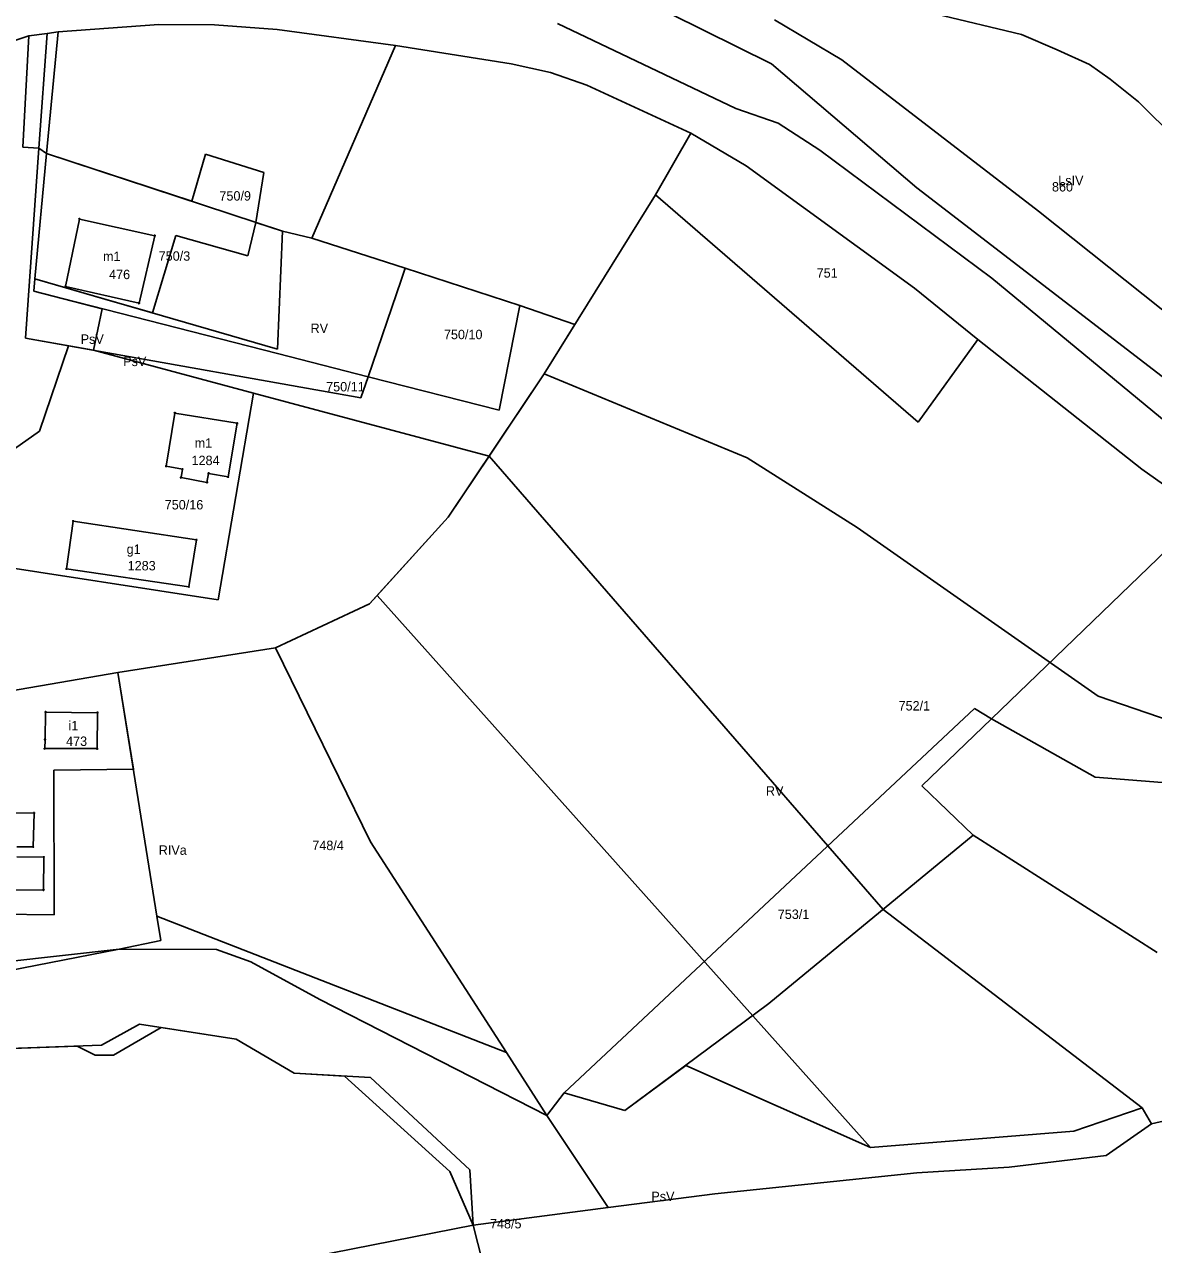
# Model space of a CAD drawing. Extents: x 7498273 to 7499989, y 5499795 to 5500810.
# Drawn here: x 7498893.9 to 7499073.7, y 5500326.8 to 5500521 of the extents above; entities that cross this region are included whole.
import ezdxf

# ---------------------------------------------------------------- set-up
doc = ezdxf.new("R2010")
doc.units = 0
for name, color, linetype in [('209-oznaczenie konturu klasyfikacyjnego', 7, 'Continuous'), ('211-numer działki ewidencyjnej', 7, 'Continuous'), ('217-kontur klasyfikacyjny', 7, 'Continuous'), ('218-kontur użytku gruntowego', 7, 'Continuous'), ('219-działka ewidencyjna', 7, 'Continuous'), ('312-budynek ewidencyjny', 7, 'Continuous'), ('312-oznaczenie budynku ewidencyjnego', 7, 'Continuous'), ('312-oznaczenie budynku ewidencyjnego-Atr117', 7, 'Continuous'), ('Punkt budynku', 7, 'Continuous')]:
    doc.layers.add(name, color=color, linetype=linetype)

# ---------------------------------------------------------------- blocks, each defined once
blk = doc.blocks.new('PUNKTBUD')
blk.add_circle((0, 0), 0.09)

msp = doc.modelspace()

# ---------------------------------------------------------------- linework, layer by layer
at = {"layer": '217-kontur klasyfikacyjny'}
for points in [[(7499052.63, 5500519.38), (7499025.15, 5500526.01)], [(7499013.3, 5500521.7), (7499024.04, 5500515.33)], [(7498897.49, 5500519.54), (7498894.59, 5500519.13)], [(7498899.25, 5500519.79), (7498897.49, 5500519.54)], [(7498915.29, 5500520.95), (7498899.25, 5500519.79)], [(7498924.13, 5500520.89), (7498915.29, 5500520.95)], [(7498934.14, 5500520.18), (7498924.13, 5500520.89)], [(7498952.96, 5500517.64), (7498934.14, 5500520.18)], [(7499058.33, 5500516.93), (7499052.63, 5500519.38)], [(7498894.59, 5500519.13), (7498885.18, 5500516.08)], [(7498971.38, 5500514.69), (7498952.96, 5500517.64)], [(7499024.04, 5500515.33), (7499055.34, 5500491.27)], [(7499063.46, 5500514.6), (7499058.33, 5500516.93)], [(7498977.66, 5500513.32), (7498971.38, 5500514.69)], [(7499066.72, 5500512.27), (7499063.46, 5500514.6)], [(7498983.45, 5500511.3), (7498977.66, 5500513.32)], [(7499071.27, 5500508.65), (7499066.72, 5500512.27)], [(7499000.01, 5500503.64), (7498983.45, 5500511.3)], [(7499101.66, 5500478.53), (7499071.27, 5500508.65)], [(7499008.77, 5500498.48), (7499000.01, 5500503.64)], [(7498893.65, 5500501.42), (7498896.19, 5500501.25)], [(7498896.19, 5500501.25), (7498894.04, 5500471.05)], [(7498895.55, 5500480.48), (7498897.42, 5500500.41)], [(7498897.42, 5500500.41), (7498896.19, 5500501.25)], [(7498897.42, 5500500.41), (7498920.54, 5500492.82)], [(7498920.54, 5500492.82), (7498922.7, 5500500.32)], [(7498922.7, 5500500.32), (7498932.02, 5500497.39)], [(7499035.61, 5500479), (7499008.77, 5500498.48)], [(7498932.02, 5500497.39), (7498930.74, 5500489.47)], [(7499055.34, 5500491.27), (7499080.34, 5500471.35)], [(7498930.74, 5500489.47), (7498929.44, 5500484.15)], [(7498934.98, 5500488.08), (7498930.74, 5500489.47)], [(7498918.01, 5500487.35), (7498914.31, 5500475.05)], [(7498929.44, 5500484.15), (7498918.01, 5500487.35)], [(7498939.66, 5500486.96), (7498934.98, 5500488.08)], [(7498954.51, 5500482.16), (7498939.66, 5500486.96)], [(7498895.37, 5500478.49), (7498895.55, 5500480.48)], [(7498906.68, 5500477.26), (7498895.55, 5500480.48)], [(7498972.75, 5500476.25), (7498954.51, 5500482.16)], [(7498906.28, 5500475.71), (7498895.37, 5500478.49)], [(7499045.66, 5500470.84), (7499035.61, 5500479)], [(7498914.31, 5500475.05), (7498906.68, 5500477.26)], [(7498904.87, 5500469.13), (7498906.28, 5500475.71)], [(7498981.53, 5500473.22), (7498972.75, 5500476.25)], [(7498976.63, 5500465.35), (7498981.53, 5500473.22)], [(7498894.04, 5500471.05), (7498904.87, 5500469.13)], [(7499071.81, 5500450.17), (7499045.66, 5500470.84)], [(7498904.87, 5500469.13), (7498930.36, 5500462.29)], [(7498976.63, 5500465.35), (7498967.86, 5500452.25)], [(7499008.94, 5500452.01), (7498976.63, 5500465.35)], [(7498930.36, 5500462.29), (7498924.73, 5500429.39)], [(7498930.36, 5500462.29), (7498967.86, 5500452.25)], [(7498967.86, 5500452.25), (7498961.36, 5500442.54)], [(7498967.86, 5500452.25), (7499030.59, 5500380.1)], [(7499026.48, 5500440.9), (7499008.94, 5500452.01)], [(7499081.74, 5500443.12), (7499071.81, 5500450.17)], [(7498961.36, 5500442.54), (7498950.04, 5500430.08)], [(7499064.84, 5500414.07), (7499026.48, 5500440.9)], [(7498924.73, 5500429.39), (7498886.87, 5500435.24)], [(7498950.04, 5500430.08), (7498948.84, 5500428.77)], [(7498950.04, 5500430.08), (7499028.61, 5500342.19)], [(7498948.84, 5500428.77), (7498933.86, 5500421.77)], [(7498933.86, 5500421.77), (7498908.79, 5500417.83)], [(7498883.78, 5500413.51), (7498908.79, 5500417.83)], [(7498908.79, 5500417.83), (7498911.24, 5500402.45)], [(7499090.07, 5500405.4), (7499064.84, 5500414.07)], [(7498911.24, 5500402.45), (7498898.57, 5500402.29)], [(7498898.57, 5500402.29), (7498898.64, 5500379.25)], [(7498898.64, 5500379.25), (7498881.05, 5500379.45)], [(7499030.59, 5500380.1), (7499071.84, 5500348.54)], [(7498908.98, 5500373.76), (7498863.81, 5500368.75)], [(7498924.46, 5500373.71), (7498908.98, 5500373.76)], [(7498929.93, 5500371.77), (7498924.46, 5500373.71)], [(7498940.91, 5500365.79), (7498929.93, 5500371.77)], [(7498977.07, 5500347.3), (7498940.91, 5500365.79)], [(7498915.64, 5500361.32), (7498908.07, 5500356.93)], [(7498927.58, 5500359.44), (7498915.64, 5500361.32)], [(7498902.28, 5500358.34), (7498888.92, 5500357.87)], [(7498905.14, 5500356.92), (7498902.28, 5500358.34)], [(7498936.85, 5500354.04), (7498927.58, 5500359.44)], [(7498908.07, 5500356.93), (7498905.14, 5500356.92)], [(7498999.17, 5500355.28), (7498989.5, 5500348.09)], [(7499028.61, 5500342.19), (7498999.17, 5500355.28)], [(7498944.86, 5500353.58), (7498936.85, 5500354.04)], [(7498961.64, 5500338.37), (7498944.86, 5500353.58)], [(7498979.8, 5500350.9), (7498977.07, 5500347.3)], [(7498989.5, 5500348.09), (7498979.8, 5500350.9)], [(7499060.98, 5500344.83), (7499071.84, 5500348.54)], [(7499071.84, 5500348.54), (7499073.33, 5500345.99)], [(7498977.07, 5500347.3), (7498986.83, 5500332.68)], [(7499028.61, 5500342.19), (7499060.98, 5500344.83)], [(7499073.33, 5500345.99), (7499066.13, 5500340.92)], [(7499066.13, 5500340.92), (7499050.64, 5500339.09)], [(7499050.64, 5500339.09), (7499035.94, 5500338.2)], [(7498965.33, 5500329.84), (7498961.64, 5500338.37)], [(7499035.94, 5500338.2), (7499003.8, 5500334.85)], [(7499003.8, 5500334.85), (7498986.83, 5500332.68)], [(7498986.83, 5500332.68), (7498965.33, 5500329.84)]]:
    msp.add_lwpolyline(points, dxfattribs=at)
at = {"layer": '218-kontur użytku gruntowego'}
for points in [[(7499012.84, 5500514.68), (7498991.26, 5500525.39)], [(7499052.63, 5500519.38), (7499025.15, 5500526.01)], [(7499013.3, 5500521.7), (7499024.04, 5500515.33)], [(7498894.59, 5500519.13), (7498897.49, 5500519.54)], [(7498897.49, 5500519.54), (7498899.25, 5500519.79)], [(7498899.25, 5500519.79), (7498915.29, 5500520.95)], [(7498915.29, 5500520.95), (7498924.13, 5500520.89)], [(7498924.13, 5500520.89), (7498934.14, 5500520.18)], [(7498934.14, 5500520.18), (7498952.96, 5500517.64)], [(7499007.17, 5500507.58), (7498978.75, 5500521.1)], [(7499058.33, 5500516.93), (7499052.63, 5500519.38)], [(7498885.18, 5500516.08), (7498894.59, 5500519.13)], [(7498952.96, 5500517.64), (7498971.38, 5500514.69)], [(7499024.04, 5500515.33), (7499055.34, 5500491.27)], [(7499063.46, 5500514.6), (7499058.33, 5500516.93)], [(7498971.38, 5500514.69), (7498977.66, 5500513.32)], [(7499035.99, 5500494.95), (7499012.84, 5500514.68)], [(7499066.72, 5500512.27), (7499063.46, 5500514.6)], [(7498977.66, 5500513.32), (7498983.45, 5500511.3)], [(7499071.27, 5500508.65), (7499066.72, 5500512.27)], [(7498983.45, 5500511.3), (7499000.01, 5500503.64)], [(7499013.89, 5500505.24), (7499007.17, 5500507.58)], [(7499101.66, 5500478.53), (7499071.27, 5500508.65)], [(7499020.5, 5500500.94), (7499013.89, 5500505.24)], [(7499000.01, 5500503.64), (7499008.77, 5500498.48)], [(7498893.65, 5500501.42), (7498896.19, 5500501.25)], [(7498896.19, 5500501.25), (7498894.04, 5500471.05)], [(7498895.55, 5500480.48), (7498897.42, 5500500.41)], [(7498897.42, 5500500.41), (7498896.19, 5500501.25)], [(7498920.54, 5500492.82), (7498897.42, 5500500.41)], [(7498922.7, 5500500.32), (7498920.54, 5500492.82)], [(7498932.02, 5500497.39), (7498922.7, 5500500.32)], [(7499047.93, 5500480.59), (7499020.5, 5500500.94)], [(7499008.77, 5500498.48), (7499035.61, 5500479)], [(7498930.74, 5500489.47), (7498932.02, 5500497.39)], [(7499085.38, 5500457), (7499035.99, 5500494.95)], [(7499055.34, 5500491.27), (7499080.34, 5500471.35)], [(7498930.74, 5500489.47), (7498929.44, 5500484.15)], [(7498934.98, 5500488.08), (7498930.74, 5500489.47)], [(7498918.01, 5500487.35), (7498914.31, 5500475.05)], [(7498929.44, 5500484.15), (7498918.01, 5500487.35)], [(7498939.66, 5500486.96), (7498934.98, 5500488.08)], [(7498954.51, 5500482.16), (7498939.66, 5500486.96)], [(7498895.37, 5500478.49), (7498895.55, 5500480.48)], [(7498906.68, 5500477.26), (7498895.55, 5500480.48)], [(7498972.75, 5500476.25), (7498954.51, 5500482.16)], [(7499079.66, 5500454.39), (7499047.93, 5500480.59)], [(7498906.28, 5500475.71), (7498895.37, 5500478.49)], [(7499035.61, 5500479), (7499045.66, 5500470.84)], [(7498914.31, 5500475.05), (7498906.68, 5500477.26)], [(7498904.87, 5500469.13), (7498906.28, 5500475.71)], [(7498981.53, 5500473.22), (7498972.75, 5500476.25)], [(7498976.63, 5500465.35), (7498981.53, 5500473.22)], [(7498894.04, 5500471.05), (7498904.87, 5500469.13)], [(7499045.66, 5500470.84), (7499071.81, 5500450.17)], [(7498904.87, 5500469.13), (7498930.36, 5500462.29)], [(7498967.86, 5500452.25), (7498976.63, 5500465.35)], [(7499008.94, 5500452.01), (7498976.63, 5500465.35)], [(7498930.36, 5500462.29), (7498924.73, 5500429.39)], [(7498930.36, 5500462.29), (7498967.86, 5500452.25)], [(7498967.86, 5500452.25), (7498961.36, 5500442.54)], [(7499030.59, 5500380.1), (7498967.86, 5500452.25)], [(7499026.48, 5500440.9), (7499008.94, 5500452.01)], [(7499071.81, 5500450.17), (7499081.74, 5500443.12)], [(7498961.36, 5500442.54), (7498950.04, 5500430.08)], [(7499064.84, 5500414.07), (7499026.48, 5500440.9)], [(7498924.73, 5500429.39), (7498886.87, 5500435.24)], [(7498950.04, 5500430.08), (7498948.84, 5500428.77)], [(7498950.04, 5500430.08), (7499028.61, 5500342.19)], [(7498948.84, 5500428.77), (7498933.86, 5500421.77)], [(7498933.86, 5500421.77), (7498908.79, 5500417.83)], [(7498908.79, 5500417.83), (7498883.78, 5500413.51)], [(7498911.24, 5500402.45), (7498908.79, 5500417.83)], [(7499090.07, 5500405.4), (7499064.84, 5500414.07)], [(7498898.57, 5500402.29), (7498911.24, 5500402.45)], [(7498898.64, 5500379.25), (7498898.57, 5500402.29)], [(7498881.05, 5500379.45), (7498898.64, 5500379.25)], [(7499071.84, 5500348.54), (7499030.59, 5500380.1)], [(7498908.98, 5500373.76), (7498863.81, 5500368.75)], [(7498924.46, 5500373.71), (7498908.98, 5500373.76)], [(7498929.93, 5500371.77), (7498924.46, 5500373.71)], [(7498940.91, 5500365.79), (7498929.93, 5500371.77)], [(7498977.07, 5500347.3), (7498940.91, 5500365.79)], [(7498915.64, 5500361.32), (7498908.07, 5500356.93)], [(7498927.58, 5500359.44), (7498915.64, 5500361.32)], [(7498902.28, 5500358.34), (7498888.92, 5500357.87)], [(7498905.14, 5500356.92), (7498902.28, 5500358.34)], [(7498936.85, 5500354.04), (7498927.58, 5500359.44)], [(7498908.07, 5500356.93), (7498905.14, 5500356.92)], [(7498999.17, 5500355.28), (7498989.5, 5500348.09)], [(7499028.61, 5500342.19), (7498999.17, 5500355.28)], [(7498944.86, 5500353.58), (7498936.85, 5500354.04)], [(7498961.64, 5500338.37), (7498944.86, 5500353.58)], [(7498979.8, 5500350.9), (7498977.07, 5500347.3)], [(7498989.5, 5500348.09), (7498979.8, 5500350.9)], [(7499071.84, 5500348.54), (7499060.98, 5500344.83)], [(7499073.33, 5500345.99), (7499071.84, 5500348.54)], [(7498977.07, 5500347.3), (7498986.83, 5500332.68)], [(7499060.98, 5500344.83), (7499028.61, 5500342.19)], [(7499066.13, 5500340.92), (7499073.33, 5500345.99)], [(7499050.64, 5500339.09), (7499066.13, 5500340.92)], [(7499035.94, 5500338.2), (7499050.64, 5500339.09)], [(7498965.33, 5500329.84), (7498961.64, 5500338.37)], [(7499003.8, 5500334.85), (7499035.94, 5500338.2)], [(7498986.83, 5500332.68), (7499003.8, 5500334.85)], [(7498986.83, 5500332.68), (7498965.33, 5500329.84)]]:
    msp.add_lwpolyline(points, dxfattribs=at)
at = {"layer": '219-działka ewidencyjna'}
for points in [[(7499052.63, 5500519.38), (7499025.15, 5500526.01)], [(7499024.04, 5500515.33), (7499013.3, 5500521.7)], [(7498894.59, 5500519.13), (7498897.49, 5500519.54)], [(7498896.19, 5500501.25), (7498897.49, 5500519.54)], [(7498897.42, 5500500.41), (7498899.25, 5500519.79)], [(7498897.49, 5500519.54), (7498899.25, 5500519.79)], [(7498915.29, 5500520.95), (7498899.25, 5500519.79)], [(7498915.29, 5500520.95), (7498924.13, 5500520.89)], [(7498924.13, 5500520.89), (7498934.14, 5500520.18)], [(7498934.14, 5500520.18), (7498952.96, 5500517.64)], [(7499052.63, 5500519.38), (7499058.33, 5500516.93)], [(7498885.18, 5500516.08), (7498894.59, 5500519.13)], [(7498894.59, 5500519.13), (7498893.65, 5500501.42)], [(7498939.66, 5500486.96), (7498952.96, 5500517.64)], [(7498952.96, 5500517.64), (7498971.38, 5500514.69)], [(7499024.04, 5500515.33), (7499055.34, 5500491.27)], [(7499058.33, 5500516.93), (7499063.46, 5500514.6)], [(7498977.66, 5500513.32), (7498971.38, 5500514.69)], [(7499063.46, 5500514.6), (7499066.72, 5500512.27)], [(7498977.66, 5500513.32), (7498983.45, 5500511.3)], [(7499066.72, 5500512.27), (7499071.27, 5500508.65)], [(7498983.45, 5500511.3), (7499000.01, 5500503.64)], [(7499071.27, 5500508.65), (7499101.66, 5500478.53)], [(7499000.01, 5500503.64), (7498994.38, 5500493.86)], [(7499000.01, 5500503.64), (7499008.77, 5500498.48)], [(7498894.04, 5500471.05), (7498896.19, 5500501.25)], [(7498895.55, 5500480.48), (7498897.42, 5500500.41)], [(7498934.98, 5500488.08), (7498897.42, 5500500.41)], [(7499008.77, 5500498.48), (7499035.61, 5500479)], [(7498976.63, 5500465.35), (7498994.38, 5500493.86)], [(7498994.38, 5500493.86), (7499036.19, 5500457.69)], [(7499055.34, 5500491.27), (7499080.34, 5500471.35)], [(7498934.98, 5500488.08), (7498934.19, 5500469.3)], [(7498939.66, 5500486.96), (7498954.51, 5500482.16)], [(7498895.37, 5500478.49), (7498895.55, 5500480.48)], [(7498895.55, 5500480.48), (7498934.19, 5500469.3)], [(7498953.87, 5500480.26), (7498954.51, 5500482.16)], [(7498954.51, 5500482.16), (7498972.75, 5500476.25)], [(7498895.37, 5500478.49), (7498934.16, 5500468.59)], [(7498948.61, 5500464.9), (7498953.87, 5500480.26)], [(7499035.61, 5500479), (7499045.66, 5500470.84)], [(7498969.49, 5500459.58), (7498972.75, 5500476.25)], [(7498894.04, 5500471.05), (7498900.92, 5500469.81)], [(7499036.19, 5500457.69), (7499045.66, 5500470.84)], [(7499045.66, 5500470.84), (7499071.81, 5500450.17)], [(7498896.27, 5500456.23), (7498900.92, 5500469.81)], [(7498947.47, 5500461.56), (7498900.92, 5500469.81)], [(7498934.16, 5500468.59), (7498948.61, 5500464.9)], [(7498947.47, 5500461.56), (7498948.61, 5500464.9)], [(7498948.61, 5500464.9), (7498969.49, 5500459.58)], [(7498961.36, 5500442.54), (7498976.63, 5500465.35)], [(7498890.52, 5500452.15), (7498896.27, 5500456.23)], [(7499071.81, 5500450.17), (7499081.74, 5500443.12)], [(7498948.84, 5500428.77), (7498961.36, 5500442.54)], [(7499058.06, 5500420.25), (7499081.74, 5500443.12)], [(7498933.86, 5500421.77), (7498948.84, 5500428.77)], [(7498908.79, 5500417.83), (7498933.86, 5500421.77)], [(7498933.86, 5500421.77), (7498948.98, 5500390.87)], [(7499047.85, 5500410.45), (7499058.06, 5500420.25)], [(7498883.78, 5500413.51), (7498908.79, 5500417.83)], [(7498908.79, 5500417.83), (7498914.96, 5500379.03)], [(7498979.8, 5500350.9), (7499045.13, 5500412.08)], [(7499036.75, 5500399.8), (7499047.85, 5500410.45)], [(7499045.13, 5500412.08), (7499047.85, 5500410.45)], [(7499047.85, 5500410.45), (7499064.37, 5500401.18)], [(7499064.37, 5500401.18), (7499079.03, 5500399.99)], [(7499036.75, 5500399.8), (7499044.92, 5500391.92)], [(7499012.42, 5500365.12), (7499044.92, 5500391.92)], [(7499044.92, 5500391.92), (7499074.23, 5500373.25)], [(7498948.98, 5500390.87), (7498970.66, 5500357.32)], [(7498914.96, 5500379.03), (7498915.63, 5500375.16)], [(7498914.96, 5500379.03), (7498970.66, 5500357.32)], [(7498908.98, 5500373.76), (7498810.76, 5500354.62)], [(7498908.98, 5500373.76), (7498915.63, 5500375.16)], [(7499012.42, 5500365.12), (7498989.5, 5500348.09)], [(7498906.19, 5500358.48), (7498912.2, 5500361.86)], [(7498912.2, 5500361.86), (7498927.58, 5500359.44)], [(7498906.19, 5500358.48), (7498885.55, 5500357.75)], [(7498936.85, 5500354.04), (7498927.58, 5500359.44)], [(7498977.07, 5500347.3), (7498970.66, 5500357.32)], [(7498936.85, 5500354.04), (7498949, 5500353.34)], [(7498949, 5500353.34), (7498964.8, 5500338.67)], [(7498979.8, 5500350.9), (7498989.5, 5500348.09)], [(7499073.33, 5500345.99), (7499090.25, 5500349.85)], [(7498977.07, 5500347.3), (7498986.83, 5500332.68)], [(7499073.33, 5500345.99), (7499066.13, 5500340.92)], [(7499050.64, 5500339.09), (7499066.13, 5500340.92)], [(7498964.8, 5500338.67), (7498965.33, 5500329.84)], [(7499035.94, 5500338.2), (7499050.64, 5500339.09)], [(7499003.8, 5500334.85), (7499035.94, 5500338.2)], [(7498986.83, 5500332.68), (7499003.8, 5500334.85)], [(7498986.83, 5500332.68), (7498965.33, 5500329.84)], [(7498936.44, 5500324.2), (7498965.33, 5500329.84)], [(7498965.33, 5500329.84), (7498973.24, 5500298.81)]]:
    msp.add_lwpolyline(points, dxfattribs=at)
at = {"layer": '312-budynek ewidencyjny'}
for points in [[(7498900.42, 5500479.26), (7498902.65, 5500490)], [(7498902.65, 5500490), (7498914.63, 5500487.34)], [(7498914.63, 5500487.34), (7498912.14, 5500476.61)], [(7498912.14, 5500476.61), (7498900.42, 5500479.26)], [(7498916.47, 5500450.65), (7498917.83, 5500459.12)], [(7498917.83, 5500459.12), (7498927.76, 5500457.48)], [(7498927.76, 5500457.48), (7498926.33, 5500448.95)], [(7498919.07, 5500450.17), (7498916.47, 5500450.65)], [(7498918.83, 5500448.85), (7498919.07, 5500450.17)], [(7498923.22, 5500449.51), (7498922.96, 5500448.08)], [(7498926.33, 5500448.95), (7498923.22, 5500449.51)], [(7498922.96, 5500448.08), (7498918.83, 5500448.85)], [(7498900.59, 5500434.32), (7498901.65, 5500441.92)], [(7498901.65, 5500441.92), (7498921.29, 5500438.94)], [(7498921.29, 5500438.94), (7498920.08, 5500431.47)], [(7498920.08, 5500431.47), (7498900.59, 5500434.32)], [(7498897.18, 5500407.15), (7498897.26, 5500411.53)], [(7498897.26, 5500411.53), (7498905.53, 5500411.42)], [(7498905.53, 5500411.42), (7498905.47, 5500405.7)], [(7498897.12, 5500405.71), (7498897.18, 5500407.15)], [(7498905.47, 5500405.7), (7498897.12, 5500405.71)], [(7498884.06, 5500395.55), (7498895.42, 5500395.45)], [(7498895.42, 5500395.45), (7498895.3, 5500390.06)], [(7498895.3, 5500390.06), (7498892.7, 5500390.08)], [(7498892.68, 5500388.48), (7498896.98, 5500388.44)], [(7498896.98, 5500388.44), (7498896.93, 5500383.19)], [(7498896.93, 5500383.19), (7498891.28, 5500383.25)]]:
    msp.add_lwpolyline(points, dxfattribs=at)

# ---------------------------------------------------------------- block references
at = {"layer": 'Punkt budynku'}
for p in [(7498902.65, 5500490), (7498914.63, 5500487.34), (7498900.42, 5500479.26), (7498912.14, 5500476.61), (7498917.83, 5500459.12), (7498927.76, 5500457.48), (7498916.47, 5500450.65), (7498919.07, 5500450.17), (7498923.22, 5500449.51), (7498918.83, 5500448.85), (7498922.96, 5500448.08), (7498926.33, 5500448.95), (7498901.65, 5500441.92), (7498921.29, 5500438.94), (7498900.59, 5500434.32), (7498920.08, 5500431.47), (7498897.26, 5500411.53), (7498905.53, 5500411.42), (7498897.18, 5500407.15), (7498897.12, 5500405.71), (7498905.47, 5500405.7), (7498895.42, 5500395.45), (7498895.3, 5500390.06), (7498896.98, 5500388.44), (7498896.93, 5500383.19)]:
    msp.add_blockref('PUNKTBUD', p, dxfattribs=at)

# ---------------------------------------------------------------- texts
at = {"layer": '209-oznaczenie konturu klasyfikacyjnego'}
for s, p in [('LsIV', (7499058.48, 5500495.38)), ('RV', (7498939.45, 5500471.86)), ('PsV', (7498902.85, 5500470.13)), ('PsV', (7498909.62, 5500466.59)), ('RV', (7499011.94, 5500398.22)), ('RIVa', (7498915.28, 5500388.8)), ('PsV', (7498993.7, 5500333.68))]:
    msp.add_text(s, height=1.5, dxfattribs=at).set_placement(p)
at = {"layer": '211-numer działki ewidencyjnej'}
for s, p in [('860', (7499057.48, 5500494.38)), ('750/9', (7498924.94, 5500492.93)), ('750/3', (7498915.27, 5500483.36)), ('751', (7499020.02, 5500480.67)), ('750/10', (7498960.68, 5500470.87)), ('750/11', (7498941.93, 5500462.56)), ('750/16', (7498916.23, 5500443.77)), ('752/1', (7499033.06, 5500411.77)), ('748/4', (7498939.73, 5500389.55)), ('753/1', (7499013.83, 5500378.59)), ('748/5', (7498968.01, 5500329.34))]:
    msp.add_text(s, height=1.5, dxfattribs=at).set_placement(p)
at = {"layer": '312-oznaczenie budynku ewidencyjnego'}
for s, p in [('476', (7498907.37, 5500480.43)), ('1284', (7498920.5, 5500450.83)), ('1283', (7498910.33, 5500434.07)), ('473', (7498900.53, 5500406.13))]:
    msp.add_text(s, height=1.5, dxfattribs=at).set_placement(p)
at = {"layer": '312-oznaczenie budynku ewidencyjnego-Atr117'}
for s, p in [('m1', (7498906.405, 5500483.31)), ('m1', (7498920.995, 5500453.6)), ('g1', (7498910.169, 5500436.7)), ('i1', (7498900.912, 5500408.62))]:
    msp.add_text(s, height=1.5, dxfattribs=at).set_placement(p)

doc.saveas('drawing.dxf')
